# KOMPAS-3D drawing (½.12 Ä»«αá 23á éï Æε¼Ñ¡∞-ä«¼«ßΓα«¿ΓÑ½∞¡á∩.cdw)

Views: Вид 1, Вид 2, Вид 3, Вид 4
Referenced files: Подвеска ВЧ-заградителя.cdw
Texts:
  Текст на чертеже
  Размерные надписи
  Шероховатость
  Линия-выноска #1
  Линия-выноска #2
  Линия-выноска #3
  Отклонения формы и база
  Заголовок таблицы
  Ячейка таблицы
  Стрелка вида
  Обозначение изменения
  Фигурная скобка
  Номер узла
  Марка координационной оси
  VRCB
  Выносная надпись
  Обозначение узла
  Марка/позиционное обозначение с линией-выноской
  Марка/позиционное обозначение на линии
  Марка/позиционное обозначение без линии-выноски
  ООббыыччнныыйй
  Definition Term
  Definition List
  Address
  Blockquote
  Preformatted
  Courier New
  z-Bottom of Form
  z-Top of Form
  Лит-Масса-Масштаб
  Материал-Предприятие
  Title Specification
  Body Specification ( left align )
  Body Specificaton ( centered )
  Без имени
  SPEC
  Normal
  Txt
  Body Text
  heading 1
  Знак Знак Знак Знак Знак Знак
  Verdana
  Simplex
  TXT
  txt
  MS Sans Serif
  Additional DXF text style 0
  Обычный
  Термин
  Список определений
  Адрес
  Цитаты
  Форматированный
  Z-конец формы
  Z-начало формы
  ТекстШаг1
  Title
  Денис
  header
  heading 2
  AGOpus
  footer
  NormalParagraphStyle
  Body Text 3
  ссылки
  Подпись в квадратике
  табл
  цепи
  Маркировка
  клеммы, контакты
  тексты табл
  Тексты. 3,2
  ЗОНА_привяз
  текст переноса
  ТТееррммиинн
  ССппииссоокк ооппррееддееллеенниийй
  ААддрреесс
  ЦЦииттааттыы
  ФФооррммааттиирроовваанннныыйй
  Z-ккооннеецц ффооррммыы
  Z-ннааччааллоо ффооррммыы
  GOST 2.304 type A
  rustxt
  heading 8
  heading 3
  heading 6
  heading 7
  russ
  Абзац Знак
  heading 4
  heading 5
  heading 9
  HeliosLight
  Pa3
  Pa1
  Три с половиной
  style2
  Шрифт 2.5
  Заголовки
  RUSTXT
  Table Contents
  Table Heading
  ГОСТ_МНЕ
  ESK - Обозначение
  маркировка
  ISOCP
  ROMANS
  SIMPLEX
  Обычный (веб)
  Текст 3,5
  Tahoma
  CNBNDG+TimesNewRoman
  Subtitle
  ISOCPEUR
  FR5
  romans
  Подписи
  Схема монтажа ВЧ-заградителя на опору №23а.
  Отпайка ВЛ-110 кВ Тюмень - Домостроительная на ПС Ембаево
  Кран КС-35719-1-02
  Примечание - примечания см. 16/01-ПОС, л.10.
  CONTINUOUS_RGB_0_0_0_THICK_0.13
  GOST2.303 4_RGB_0_0_0_SC_0.04_THICK_0.13
  CONTINUOUS_RGB_0_0_0_THICK_0.18
  CONTINUOUS_RGB_173_173_173_THICK_0.13
  GOST2.303 4_RGB_173_173_173_SC_0.04_THICK_0.13
  СONTINUOUS_RGB_0_0_0_THICK_0.13
  POLYLINE_STYLE_0.30_RGB_0_0_0
  CONTINUOUS_RGB_0_0_0_THICK_0.3
  GOST2.303 6_RGB_0_0_0_SC_0.04_THICK_0.13
  POLYLINE_STYLE_0.18_RGB_0_0_0
  GOST2.303 6_RGB_0_0_0_SC_0_THICK_0.18
  K5LT_AXLED_RGB_255_128_0_SC_1_THICK_0.18
  CONTINUOUS_RGB_0_0_0_THICK_0.25
  POLYLINE_STYLE_0.21_RGB_0_0_0
  СONTINUOUS_RGB_0_0_0_THICK_0.18
  POLYLINE_STYLE_0.50_RGB_0_0_0
  POLYLINE_STYLE_0.40_RGB_0_0_0
  CONTINUOUS_RGB_0_0_0_THICK_0.6
  Стили документа
  Автомобильный кран КС-35714
  Ромин
  Подвеска ВЧ-заградителя
  на опоре № 23а
  Политова
  Разраб.
  Микрюков
  Схема пневматическая соединений
  Перезавод ВЛ на ПС Тюмень. Реконструкция устройств
  РЗ и ПА на обратных концах отходящих ВЛ,
  ВОЛС Тюменского ТПО
  Нов.
  ГИП
  Матвеев
Dimensions and other numbers on the sheet: 16/01-ПОС; 7; 3,2_; 3.5; 2.5; 2,5; 1,8; 3,2; 2,5 (контакты, клеммы); 3,2 (надписи); 3,2 (Зоны); 5; 2,5_01; 2,5_3; 3,5_01; 3,5_tabl; 5_заголовок; 2,3_; 3,2_зона не привяз; 3,5; 3.2 маркировка; 3,2 элементы; 3,2 линия; 3,2 таблица; 2,5 грязносинь; 2.5 курсив; 2.5_Э5_надписи; 2.5_Э5_ссылки; 2.5_кабель; 3.2; 2.5 надписи; 3 и 5; 5,0_белый_подчёркнутый; 3.2 фиол; 3.2 (текст); 10500; 4000; 4800; 3000; 6200; 12; 4; 05.14; -091-02-ЭП-; 3; 253-14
